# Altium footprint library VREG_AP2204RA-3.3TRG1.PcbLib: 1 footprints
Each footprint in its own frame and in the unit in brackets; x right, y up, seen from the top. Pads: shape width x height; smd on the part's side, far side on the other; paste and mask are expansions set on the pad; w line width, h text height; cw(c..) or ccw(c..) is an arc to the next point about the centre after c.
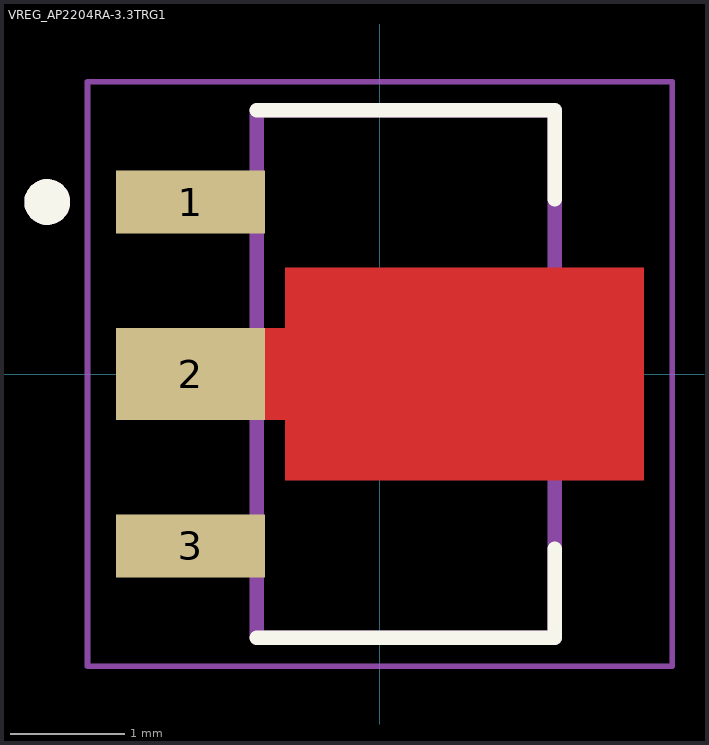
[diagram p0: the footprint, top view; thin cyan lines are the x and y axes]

## VREG_AP2204RA-3.3TRG1 [mm]
pads (3):
  rect 1.3x0.55 smd: 1(-1.65,1.5) 3(-1.65,-1.5)
  rect 1.3x0.8 smd: 2(-1.65,0)
Top Layer:
  region: 2.3,-0.925 -0.825,-0.925 -0.825,-0.4 -2.3,-0.4 -2.3,0.4 -0.825,0.4 -0.825,0.925 2.3,0.925
Top Overlay:
  circle w0.2: c-2.9,1.5 r0.1
  lines w0.127: -1.075,-2.3 1.525,-2.3 1.525,-1.524 ; -1.075,2.3 1.525,2.3 1.525,1.524
Top Paste:
  region: 1.508,-1.1 -0.032,-1.1 -0.032,1.1 1.508,1.1
Top Solder:
  region: 2.4,-1.025 -0.925,-1.025 -0.925,1.025 2.4,1.025
Mechanical 13:
  circle w0.2: c-2.9,1.5 r0.1
  lines w0.127: -1.075,-2.3 -1.075,2.3 1.525,2.3 1.525,-2.3 -1.075,-2.3
Mechanical 15:
  lines w0.05: -2.55,-2.55 -2.55,2.55 2.55,2.55 2.55,-2.55 -2.55,-2.55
